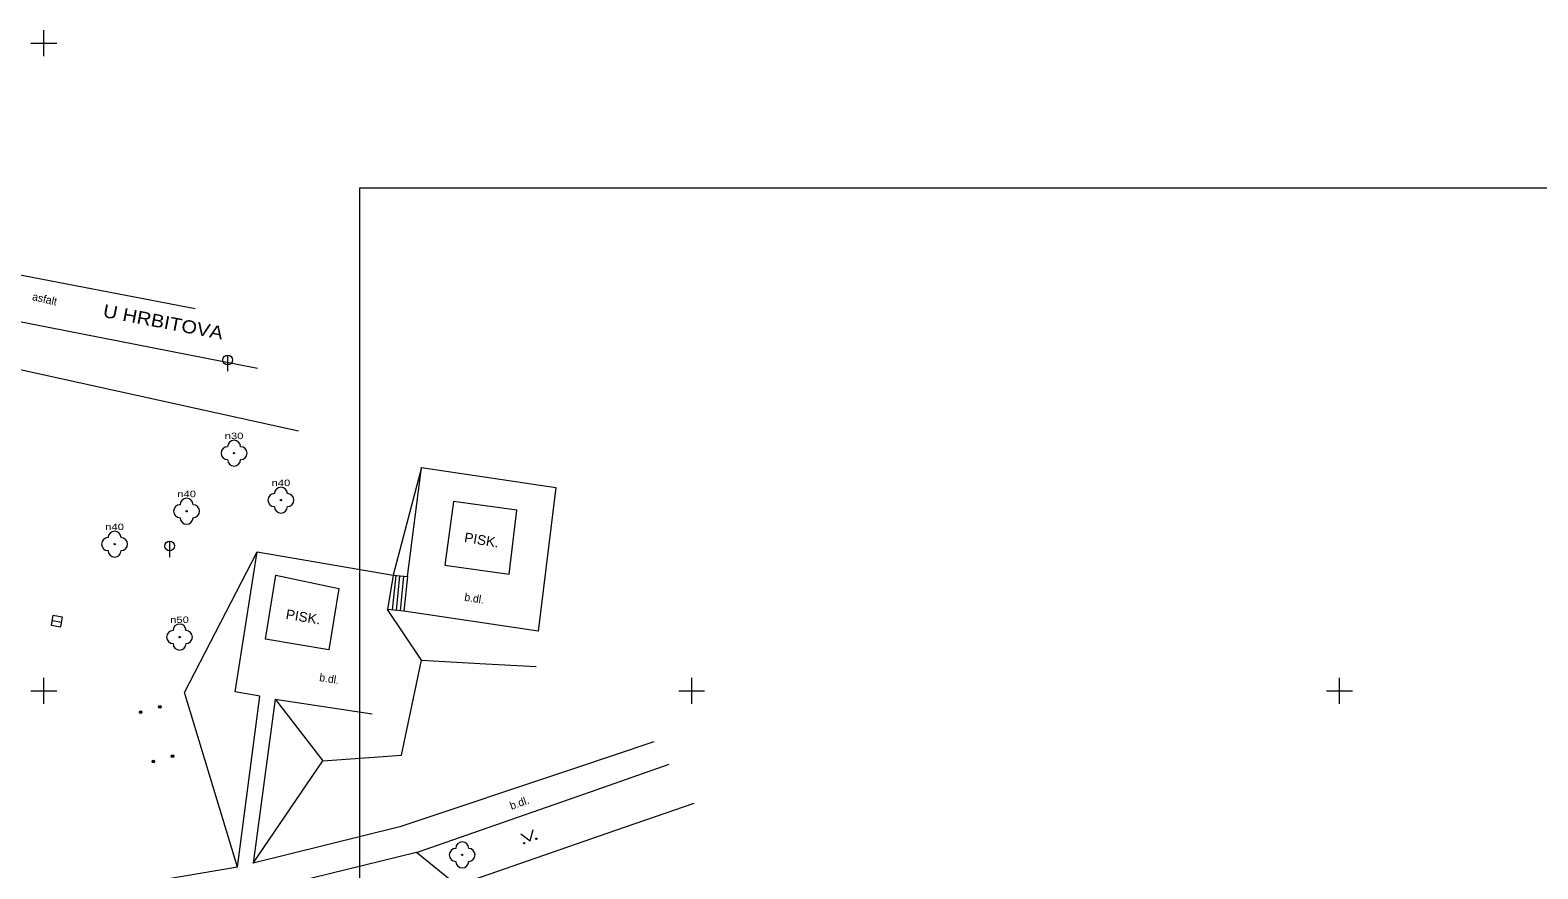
# Model space of a CAD drawing. Extents: x -670514 to -669423, y -1130798 to -1130123.
# Drawn here: x -670251.1 to -670134.7, y -1130563.7 to -1130499 of the extents above; entities that cross this region are included whole.
import ezdxf
from ezdxf.enums import TextEntityAlignment as Align

# ---------------------------------------------------------------- set-up
doc = ezdxf.new("R2010")
doc.units = 0
doc.header["$LTSCALE"] = 0.24
for name, color, linetype, lineweight in [('10', 7, 'Continuous', 13), ('14', 7, 'Continuous', 13), ('22', 7, 'Continuous', 13), ('25', 7, 'Continuous', 13), ('27', 7, 'Continuous', 13), ('36', 7, 'Continuous', 13), ('45', 7, 'Continuous', 13), ('60', 7, 'Continuous', 13), ('61', 7, 'Continuous', 13)]:
    doc.layers.add(name, color=color, linetype=linetype, lineweight=lineweight)
doc.layers.add('40', color=7, linetype='Continuous')
doc.layers.add('42', color=7, linetype='Continuous')

msp = doc.modelspace()

# ---------------------------------------------------------------- linework, layer by layer
at = {"layer": '10'}
for p, q in [((-670261.098, -1130516.117), (-670238.322, -1130520.49)), ((-670233.507, -1130525.118), (-670269.644, -1130518.026)), ((-670222.84, -1130541.085), (-670223.108, -1130543.756)), ((-670222.541, -1130541.116), (-670222.809, -1130543.783)), ((-670222.243, -1130541.148), (-670222.51, -1130543.809)), ((-670235.064, -1130563.595), (-670233.341, -1130550.417)), ((-670232.137, -1130550.64), (-670233.849, -1130563.293)), ((-670232.137, -1130550.64), (-670224.663, -1130551.782)), ((-670202.932, -1130553.939), (-670209.116, -1130556.01)), ((-670207.798, -1130557.781), (-670201.727, -1130555.656)), ((-670221.23, -1130562.482), (-670207.798, -1130557.781)), ((-670199.835, -1130558.688), (-670205.883, -1130560.786))]:
    msp.add_line(p, q, dxfattribs=at)
for points in [[(-670221.945, -1130541.179), (-670220.852, -1130532.756), (-670210.474, -1130534.305), (-670211.839, -1130545.401), (-670222.212, -1130543.836)], [(-670233.341, -1130550.417), (-670235.241, -1130550.075), (-670233.548, -1130539.254), (-670223.047, -1130541.063), (-670223.472, -1130543.724)], [(-670223.047, -1130541.063), (-670221.945, -1130541.179), (-670222.212, -1130543.836), (-670223.472, -1130543.724)], [(-670209.116, -1130556.01), (-670222.521, -1130560.499), (-670233.849, -1130563.293)], [(-670205.883, -1130560.786), (-670218.097, -1130565.022), (-670221.23, -1130562.482), (-670234.659, -1130565.78), (-670252.463, -1130568.813), (-670254.927, -1130572.4)], [(-670235.064, -1130563.595), (-670252.199, -1130566.506), (-670259.126, -1130567.839)]]:
    msp.add_lwpolyline(points, dxfattribs=at)
for points in [[(-670219.04, -1130540.301), (-670214.084, -1130540.996), (-670213.49, -1130536.058), (-670218.384, -1130535.391)], [(-670232.09, -1130541.08), (-670227.238, -1130542.109), (-670227.995, -1130546.828), (-670232.902, -1130546.011)]]:
    msp.add_lwpolyline(points, close=True, dxfattribs=at)
at = {"layer": '14'}
for p, q in [((-670230.342, -1130529.964), (-670266.359, -1130522.029)), ((-670220.852, -1130532.756), (-670223.047, -1130541.063)), ((-670220.849, -1130547.623), (-670223.472, -1130543.724)), ((-670215.88, -1130547.901), (-670211.991, -1130548.119)), ((-670232.137, -1130550.64), (-670228.469, -1130555.393))]:
    msp.add_line(p, q, dxfattribs=at)
for points in [[(-670235.064, -1130563.595), (-670239.143, -1130550.126), (-670233.548, -1130539.254)], [(-670233.849, -1130563.293), (-670228.469, -1130555.393), (-670222.385, -1130554.958), (-670220.849, -1130547.623), (-670215.88, -1130547.901)]]:
    msp.add_lwpolyline(points, dxfattribs=at)
at = {"layer": '22'}
for centre in [(-670235.317, -1130531.652), (-670238.982, -1130536.132), (-670231.702, -1130535.275), (-670244.539, -1130538.673), (-670239.526, -1130545.844), (-670217.711, -1130562.661)]:
    msp.add_circle(centre, 0.05, dxfattribs=at)
for centre, start, end in [((-670235.817, -1130531.652), 90, 270), ((-670235.317, -1130531.152), 0, 180), ((-670234.817, -1130531.652), 270, 90), ((-670235.317, -1130532.152), 180, 0), ((-670232.202, -1130535.275), 90, 270), ((-670231.702, -1130534.775), 0, 180), ((-670231.202, -1130535.275), 270, 90), ((-670239.482, -1130536.132), 90, 270), ((-670238.982, -1130535.632), 0, 180), ((-670238.482, -1130536.132), 270, 90), ((-670231.702, -1130535.775), 180, 0), ((-670238.982, -1130536.632), 180, 0), ((-670245.039, -1130538.673), 90, 270), ((-670244.539, -1130538.173), 0, 180), ((-670244.039, -1130538.673), 270, 90), ((-670244.539, -1130539.173), 180, 0), ((-670240.026, -1130545.844), 90, 270), ((-670239.526, -1130545.344), 0, 180), ((-670239.026, -1130545.844), 270, 90), ((-670239.526, -1130546.344), 180, 0), ((-670217.711, -1130562.161), 0, 180), ((-670218.211, -1130562.661), 90, 270), ((-670217.211, -1130562.661), 270, 90), ((-670217.711, -1130563.161), 180, 0)]:
    msp.add_arc(centre, 0.5, start, end, dxfattribs=at)
at = {"layer": '25'}
for centre, radius in [((-670241.046, -1130551.235), 0.1002), ((-670241.046, -1130551.235), 0.0348), ((-670242.527, -1130551.638), 0.1002), ((-670242.527, -1130551.638), 0.0348), ((-670241.549, -1130555.447), 0.1002), ((-670241.549, -1130555.447), 0.0348), ((-670240.068, -1130555.044), 0.1002), ((-670240.068, -1130555.044), 0.0348)]:
    msp.add_circle(centre, radius, dxfattribs=at)
at = {"layer": '27'}
for p, q in [((-670235.817, -1130524.083), (-670235.817, -1130525.333)), ((-670240.296, -1130538.433), (-670240.296, -1130539.683)), ((-670249.36, -1130544.559), (-670248.622, -1130544.689))]:
    msp.add_line(p, q, dxfattribs=at)
msp.add_lwpolyline([(-670249.425, -1130544.928), (-670248.686, -1130545.057), (-670248.557, -1130544.318), (-670249.296, -1130544.189)], close=True, dxfattribs=at)
for centre in [(-670235.8166, -1130524.4581), (-670240.2956, -1130538.8081)]:
    msp.add_circle(centre, 0.375, dxfattribs=at)
at = {"layer": '36'}
msp.add_lwpolyline([(-670213.177, -1130561.038), (-670212.456, -1130561.58), (-670212.234, -1130560.706)], dxfattribs=at)
for centre in [(-670212.928, -1130561.7459), (-670211.9847, -1130561.4139)]:
    msp.add_circle(centre, 0.05, dxfattribs=at)
at = {"layer": '60'}
msp.add_lwpolyline([(-670225.642, -1130798.198), (-669815.642, -1130798.198), (-669815.642, -1130511.198), (-670225.642, -1130511.198)], close=True, dxfattribs=at)
at = {"layer": '61'}
for p, q in [((-670251, -1130500), (-670249, -1130500)), ((-670250, -1130501), (-670250, -1130499)), ((-670251, -1130550), (-670249, -1130550)), ((-670250, -1130551), (-670250, -1130549)), ((-670201, -1130550), (-670199, -1130550)), ((-670200, -1130551), (-670200, -1130549)), ((-670151, -1130550), (-670149, -1130550)), ((-670150, -1130551), (-670150, -1130549))]:
    msp.add_line(p, q, dxfattribs=at)

# ---------------------------------------------------------------- texts
at = {"layer": '22', "width": 1.3}
for s, p in [('n30', (-670235.3165, -1130530.566)), ('n40', (-670231.7015, -1130534.189)), ('n40', (-670238.9815, -1130535.046)), ('n40', (-670244.5385, -1130537.587)), ('n50', (-670239.5255, -1130544.758))]:
    msp.add_text(s, height=0.499, dxfattribs=at).set_placement(p, align=Align.CENTER)
at = {"layer": '40'}
for s, rotation, p in [('asfalt', 347.052, (-670250.0007, -1130520.0444)), ('b.dl.', 351.313, (-670216.8258, -1130543.155)), ('b.dl.', 351.313, (-670228.0198, -1130549.352)), ('b.dl.', 19.289, (-670213.1966, -1130558.9285))]:
    msp.add_text(s, height=0.6, rotation=rotation, dxfattribs=at).set_placement(p, align=Align.CENTER)
at = {"layer": '42', "width": 1.05}
for p in [(-670216.2681, -1130538.7231), (-670230.0401, -1130544.6541)]:
    msp.add_text('PISK.', height=0.75, rotation=350.547, dxfattribs=at).set_placement(p, align=Align.CENTER)
at = {"layer": '45', "width": 1.15}
msp.add_text('U HRBITOVA', height=1, rotation=349.194, dxfattribs=at).set_placement((-670240.8812, -1130522.0071), align=Align.CENTER)

doc.saveas('drawing.dxf')
